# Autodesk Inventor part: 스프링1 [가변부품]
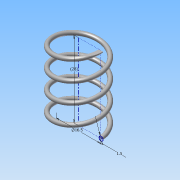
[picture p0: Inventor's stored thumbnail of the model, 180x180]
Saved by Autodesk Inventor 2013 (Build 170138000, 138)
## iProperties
Created: 2015-08
Part Number: 스프링1 [가변부품]
Material: 강철, 연강
Document SubType Name: Modeling
Designer: Administrator
Mass: 2.8364 g
Surface Area: 9.76293 cm^2
Volume: 0.360865 cm^3
Density: 7.86 g/cm^3
Author: Administrator
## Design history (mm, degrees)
sketch "스케치1"
  geometry: L1 (0, 0)-(8.25, 0); L2 (8.25, 0)-(8.25, 28); L3 (8.25, 28)-(0, 28); L4 (0, 28)-(0, 0); C1 r 0.75 at (8.25, 0)
  constraints: 8 end point, 2 parallel, 1 centre point, 1 coincident, 1 horizontal, 1 perpendicular
  dimensions: "d0" = 1.5 diameter of C1; "d2" = 16.5 diameter of L2 L4; "d3" = 28 distance of L3.end L1.start (derived)
feature "코일1" pitch "d4" = 10; turns "d6" = 4; dims "d5" = 28 (= d3), "d7" = 0, angle "d8" = 90 deg, angle "d9" = 90 deg, "d10" = 0, "d11" = 0
sketch "스케치2"
  geometry: L1 (-9, 0)-(-7.5, 0) reference; 1 further point
  constraints: 1 horizontal alignment
extrude "돌출1" cut sketch "스케치2" distance "d12" = 10; taper "d13" = 0 deg
node "작업 평면1"
sketch "스케치3"
  geometry: L1 (1.5, 0)-(0, 0) reference; 1 further point
  constraints: 1 horizontal alignment
extrude "돌출2" cut sketch "스케치3" distance "d14" = 10; taper "d15" = 0 deg
node "솔리드1"
node "절단 모서리 투영1"
node "절단 모서리 투영2"
